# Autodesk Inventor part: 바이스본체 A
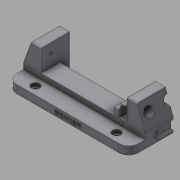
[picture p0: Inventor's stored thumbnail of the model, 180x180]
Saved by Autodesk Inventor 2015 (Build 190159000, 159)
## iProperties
Created: 2017-04
Part Number: 바이스본체 A
Material: 알루미늄 6061
Document SubType Name: Modeling
Designer: mduedu
Density: 2.71 g/cm^3
Mass: 324.199 g
Surface Area: 276.734 cm^2
Volume: 119.631 cm^3
Appearance: 기본값
Author: mduedu
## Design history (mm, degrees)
sketch "스케치1"
  geometry: L1 (-75, 0)-(75, 0); L2 (-75, 0)-(-75, 17); L3 (-53, 17)-(53, 17); L4 (75, 17)-(75, 0); L5 (-75, 17)-(-65.173, 44); L6 (-65.173, 44)-(-53, 44); L7 (-53, 44)-(-53, 17); L8 (0, 0)-(0, 17); L9 (75, 17)-(65.173, 44); L10 (65.173, 44)-(53, 44); L11 (53, 44)-(53, 17); 1 further point
  constraints: 22 end point, 4 perpendicular, 2 horizontal alignment, 2 midpoint, 2 symmetric about line, 1 coincident, 1 collinear, 1 horizontal, 1 vertical
  dimensions: "d0" = 150 distance of L1.start L1.end; "d1" = 17 distance of L1.start L2.end; "d2" = 27 distance of L3.start L6.end; "d3" = 22 distance of L3.start L2.end; "d4" = 70 deg angle of L3 L5; "d54" = 20 deg angle of L9 L4
extrude "돌출1" new body sketch "스케치1" stored distance "d5" = 70; taper "d6" = 0 deg
sketch "스케치2"
  geometry: L1 (0, 70)-(106, 70) reference; L2 (106, 70)-(106, 0) reference; L3 (106, 0)-(0, 0) reference; L4 (0, 47)-(106, 47); L5 (106, 47)-(106, 23); L6 (106, 23)-(0, 23); L7 (0, 23)-(0, 47); L8 (0, 70)-(0, 0) reference; 2 further points
  constraints: 8 end point, 2 parallel, 2 point on line, 1 horizontal, 1 horizontal alignment, 1 midpoint, 1 perpendicular
  dimensions: "d7" = 24 distance between parallel lines of L6 L4
extrude "돌출2" cut sketch "스케치2" stored distance "d9" = 70; taper "d10" = 0 deg
sketch "스케치3"
  geometry: L1 (22, -23)-(128, -23) reference; L2 (128, -47)-(22, -47) reference; L3 (22, -18)-(128, -18); L4 (128, -52)-(22, -52); L5 (22, -18)-(22, -52); L6 (128, -18)-(128, -52); 1 further point
  constraints: 8 end point, 3 parallel, 2 point on line, 1 perpendicular
  dimensions: "d11" = 5 distance between parallel lines of L3 L1; "d12" = 5 distance between parallel lines of L4 L2
extrude "돌출3" cut sketch "스케치3" distance "d13" = 12; taper "d14" = 0 deg
fillet "모깎기1" dims "d15" = 3, "d16" = 3
sketch "스케치4"
  geometry: L1 (103, 23)-(3, 23) reference; L2 (0, 26)-(0, 0) reference; L3 (106, 0)-(0, 0) reference; L4 (106, 26)-(106, 0) reference; L5 (96, 0)-(90, 0); L6 (90, 0)-(90, 19.5); L7 (96, 19.5)-(96, 0); L8 (90, 19.5)-(96, 19.5); A1 r 3 centre (3, 26) between (0, 26) and (3, 23) reference; A2 r 3 centre (103, 26) between (103, 23) and (106, 26) reference; 1 further point
  constraints: 8 end point, 2 perpendicular, 1 horizontal, 1 parallel, 1 point on line
  dimensions: "d17" = 10 distance between parallel lines of L7 L4; "d18" = 6 distance between parallel lines of L7 L6; "d27" = 3.5 distance between parallel lines of L8 L1
extrude "돌출4" join sketch "스케치4" distance "d19" = 12; taper "d20" = 0 deg
chamfer "모따기1" distance "d21" = 3; stored, may be unused: second distance "d22" = 2, angle "d23" = 45 deg
chamfer "모따기2" distance "d24" = 3; stored, may be unused: second distance "d25" = 2, angle "d26" = 45 deg
sketch "스케치5"
  geometry: L1 (-15.5, 35.8)-(-15.5, -25.8) reference; L2 (19.5, 0)-(0, 0) reference; C1 r 6.5 at (9.5, 15); 1 further point
  constraints: 1 centre point
  dimensions: "d28" = 13 diameter of C1; "d30" = 15 distance from line of C1.centre L2; "d31" = 25 distance from line of C1.centre L1
extrude "돌출5" cut sketch "스케치5" stored distance "d32" = 12; taper "d33" = 0 deg
sketch "스케치6"
  geometry: C1 r 5 at (-10, 15); C2 r 5 at (-60, 15); A1 r 6.5 centre (-10, 15) between (-15.766, 12) and (-4.234, 12) reference; A2 r 6.5 centre (-60, 15) between (-65.766, 12) and (-54.234, 12) reference; 1 further point
  constraints: 2 centre point, 2 coincident
  dimensions: "d34" = 10 diameter of C1; "d35" = 10 diameter of C2 (= d34)
extrude "돌출6" cut sketch "스케치6" stored distance "d36" = 12; taper "d37" = 0 deg
chamfer "모따기3" distance "d38" = 1; stored, may be unused: second distance "d39" = 2, angle "d40" = 45 deg
chamfer "모따기4" distance "d41" = 1; stored, may be unused: second distance "d42" = 2, angle "d43" = 45 deg
sketch "스케치7"
  geometry: L1 (-35, 35.8)-(-35, -25.8) reference; L2 (-70, 0)-(0, 0) reference; C1 r 5 at (-35, 15); 1 further point
  constraints: 1 centre point, 1 point on line
  dimensions: "d44" = 10 diameter of C1; "d45" = 15 distance from line of C1.centre L2
extrude "돌출7" cut sketch "스케치7" stored distance "d46" = 12; taper "d47" = 0 deg
chamfer "모따기5" distance "d48" = 1; stored, may be unused: second distance "d49" = 2, angle "d50" = 45 deg
node "작업축1"
sketch "스케치8"
  geometry: L1 (-105, 32)-(105, 32) reference; L2 (58, 32)-(64, 32); L3 (64, 32)-(64, 40); L4 (64, 40)-(58, 40); L5 (58, 40)-(58, 32); L6 (53, 38)-(53, 26) reference; 1 further point
  constraints: 8 end point, 2 parallel, 1 horizontal, 1 perpendicular, 1 point on line
  dimensions: "d51" = 5 distance from line of L6 L2.start; "d52" = 6 distance of L3.end L4.end; "d53" = 16 diameter of L4 L1
revolve "회전1" sketch "스케치8" stored, may be unused: angle "d55" = 90 deg
fillet "모깎기2"
chamfer "모따기6" distance "d56" = 1; stored, may be unused: second distance "d57" = 2, angle "d58" = 45 deg
sketch "스케치9"
  geometry: L1 (17.5, 3)-(52.5, 3); L2 (52.5, 13)-(17.5, 13); L3 (70, 0)-(0, 0) reference; L4 (17.5, 8)-(52.5, 8); A1 r 5 centre (17.5, 8) between (17.5, 13) and (17.5, 3); A2 r 5 centre (52.5, 8) between (52.5, 3) and (52.5, 13); 3 further points
  constraints: 6 end point, 4 point on circle, 3 tangent, 2 centre point, 2 midpoint, 2 parallel, 1 horizontal, 1 vertical alignment
  dimensions: "d59" = 35 distance of L4.start L4.end; "d61" = 5 radius of A2; "d62" = 8 distance between parallel lines of L3 L4
extrude "돌출8" cut sketch "스케치9" distance "d63" = 3; taper "d64" = 0 deg
chamfer "모따기7" distance "d65" = 1; stored, may be unused: second distance "d66" = 2, angle "d67" = 45 deg
chamfer "모따기8" distance "d68" = 1; stored, may be unused: second distance "d69" = 2, angle "d70" = 45 deg
feature "분할1"
sketch "스케치10"
  geometry: L1 (35, 27)-(0, 27) reference; L2 (0, 0)-(0, 27) reference; 1 further point
  dimensions: "d85" = 11.5 distance from line of point (12, 15.5) L1; "d86" = 12 distance from line of point (12, 15.5) L2
hole "구멍1" sketch "스케치10" at (12, 15.5) diameter "d71" = 3.242; stored, may be unused: countersink angle "d75" = 90 deg, drill point angle "d77" = 120 deg; dims "d72" = 6, "d73" = 4, "d74" = 2, "d76" = 8
sketch "스케치11"
  geometry: A1 r 5 centre (17.5, 8) between (17.5, 13) and (17.5, 3) reference; 1 further point
  constraints: 1 coincident
hole "구멍3" sketch "스케치11" at (17.5, 8) diameter "d78" = 2.459; stored, may be unused: countersink angle "d82" = 90 deg, drill point angle "d84" = 120 deg; dims "d79" = 4.5, "d80" = 4, "d81" = 2, "d83" = 6
sketch "스케치13"
  geometry: L1 (75, 0)-(75, 35) reference; L2 (-75, 0)-(-75, 35) reference; L3 (-75, 35)-(75, 35); L4 (75, 35)-(75, 55); L5 (75, 55)-(-75, 55); L6 (-75, 55)-(-75, 35); 1 further point
  constraints: 8 end point, 2 parallel, 1 horizontal, 1 perpendicular, 1 point on line
  dimensions: "d90" = 20 distance between parallel lines of L5 L3; "d94" = 150 distance of L4.end L5.end (derived)
extrude "돌출9" join sketch "스케치13" distance "d92" = 10; taper "d93" = 0 deg
sketch "스케치14"
  geometry: L1 (-75, -35)-(-75, -55) reference; L2 (75, -55)-(75, -35) reference; L3 (-75, -45)-(75, -45); 3 further points
  constraints: 2 end point, 2 midpoint, 2 point on line
  dimensions: "d95" = 50 horizontal distance of point (-50, -45) point (0, 0); "d96" = 100 distance of point (50, -45) point (-50, -45)
fillet "모깎기3" dims "d97" = 12
chamfer "모따기9" distance "d98" = 1; stored, may be unused: second distance "d99" = 2, angle "d100" = 45 deg
hole "구멍4" sketch "스케치14" diameter "d101" = 4.134; stored, may be unused: countersink angle "d105" = 90 deg, drill point angle "d107" = 118 deg; dims "d102" = 6, "d103" = 10, "d104" = 4, "d106" = 8
sketch "스케치15"
  geometry: L1 (0, 0)-(126, 0) reference; 3 further points
  constraints: 1 midpoint, 1 vertical alignment, 1 other
  dimensions: "d109" = 5 distance from line of point (63, 5) L1
feature "엠보싱2" sketch "스케치15" dims "d0" = 150, "d1" = 17, "d2" = 27, "d3" = 22, "d4" = 70 deg, "d54" = 20 deg, "d110" = 0.5, "d111" = 0
node "솔리드1"
mirror "대칭1"
mirror "대칭2"
mirror "대칭3"
mirror "대칭4"
node "투영된 루프1"
